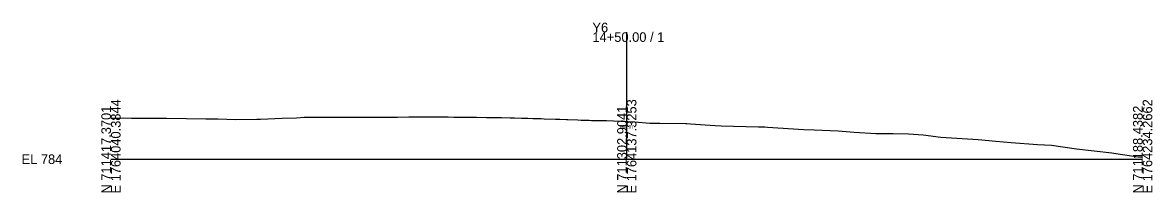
# Model space of a CAD drawing. Extents: x -26 to 1764234, y -10 to 711417.
# Drawn here: x -25.7 to 302.8, y 4490.3 to 4539.8 of the extents above; entities that cross this region are included whole.
import ezdxf

# ---------------------------------------------------------------- set-up
doc = ezdxf.new("R2010")
doc.units = 0
for name, color, linetype in [('Default', 7, 'Continuous'), ('Exist Cross Section Cell', 7, 'Continuous'), ('Exist XS Center Line Elevation Label', 7, 'Continuous'), ('Exist XS Ground Line', 7, 'Continuous')]:
    doc.layers.add(name, color=color, linetype=linetype)

msp = doc.modelspace()

# ---------------------------------------------------------------- linework, layer by layer
at = {"layer": 'Exist Cross Section Cell'}
for p, q in [((150, 4500), (150, 4537.01)), ((0, 4500), (150, 4500)), ((150, 4500), (300, 4500))]:
    msp.add_line(p, q, dxfattribs=at)
at = {"layer": 'Exist XS Ground Line'}
msp.add_lwpolyline([(0, 4512), (1.47, 4511.98), (2.77, 4511.99), (3.73, 4512.03), (5.94, 4511.97), (16.16, 4511.96), (21.99, 4511.84), (27.63, 4511.82), (31.12, 4511.78), (36.3, 4511.62), (42.41, 4511.66), (43.09, 4511.7), (43.45, 4511.71), (49.75, 4511.97), (54, 4512.11), (56.2, 4512.22), (58.64, 4512.24), (59.99, 4512.27), (60.7, 4512.27), (61.61, 4512.26), (63.23, 4512.27), (63.71, 4512.27), (66.37, 4512.27), (67.1, 4512.27), (70.27, 4512.25), (70.97, 4512.25), (73.54, 4512.24), (74.84, 4512.24), (76.82, 4512.24), (78.71, 4512.25), (80.09, 4512.27), (82.57, 4512.28), (83.37, 4512.29), (86.65, 4512.31), (87.77, 4512.31), (89.92, 4512.32), (90.31, 4512.32), (93.2, 4512.33), (94.18, 4512.34), (95.42, 4512.32), (96.47, 4512.33), (98.05, 4512.33), (99.75, 4512.3), (101.92, 4512.28), (103.03, 4512.27), (105.78, 4512.24), (106.3, 4512.24), (109.17, 4512.19), (109.65, 4512.18), (112.85, 4512.13), (113.52, 4512.12), (116.13, 4512.07), (116.71, 4512.06), (117.39, 4512.05), (119.41, 4512.01), (121.26, 4511.95), (122.68, 4511.9), (125.13, 4511.83), (125.96, 4511.8), (129.24, 4511.7), (130.57, 4511.64), (132.51, 4511.56), (132.86, 4511.54), (135.79, 4511.44), (136.73, 4511.41), (139.06, 4511.35), (139.77, 4511.33), (140.6, 4511.31), (141.54, 4511.3), (142.34, 4511.28), (143.58, 4511.25), (144.05, 4511.25), (150.27, 4510.95), (152.38, 4510.88), (156.72, 4510.55), (159.65, 4510.49), (167.09, 4510.42), (167.42, 4510.41), (168.48, 4510.33), (175.69, 4509.85), (177.41, 4509.7), (188.32, 4509.43), (190.15, 4509.4), (190.87, 4509.37), (201.44, 4508.65), (204.51, 4508.53), (211.43, 4508.23), (216.07, 4507.85), (222.41, 4507.51), (227.43, 4507.45), (231.92, 4507.43), (236.14, 4507.07), (241.35, 4506.46), (252.2, 4505.79), (257.34, 4505.26), (261.74, 4504.88), (269.39, 4504.31), (273.46, 4504.06), (280.79, 4503.05), (291.05, 4501.85), (292.25, 4501.62), (298.73, 4500.65), (300, 4500.68)], dxfattribs=at)

# ---------------------------------------------------------------- texts
at = {"layer": 'Default'}
msp.add_text('-', height=0.0001, dxfattribs=at).set_placement((0, 4500))
at = {"layer": 'Exist Cross Section Cell'}
for s, p in [('Y6', (140, 4537.01)), ('14+50.00 / 1', (140, 4534.21)), ('EL 784', (-26, 4498.6))]:
    msp.add_text(s, height=2.8, dxfattribs=at).set_placement(p)
for s, p in [('E 1764040.3844', (2.8, 4490)), ('N 711417.3701', (0, 4490)), ('N 711302.9041', (150, 4490)), ('E 1764137.3253', (152.8, 4490)), ('N 711188.4382', (300, 4490)), ('E 1764234.2662', (302.8, 4490))]:
    msp.add_text(s, height=2.8, rotation=90, dxfattribs=at).set_placement(p)
at = {"layer": 'Exist XS Center Line Elevation Label'}
msp.add_text('794.97', height=1, dxfattribs=at).set_placement((147.85, 4508.97))

doc.saveas('drawing.dxf')
